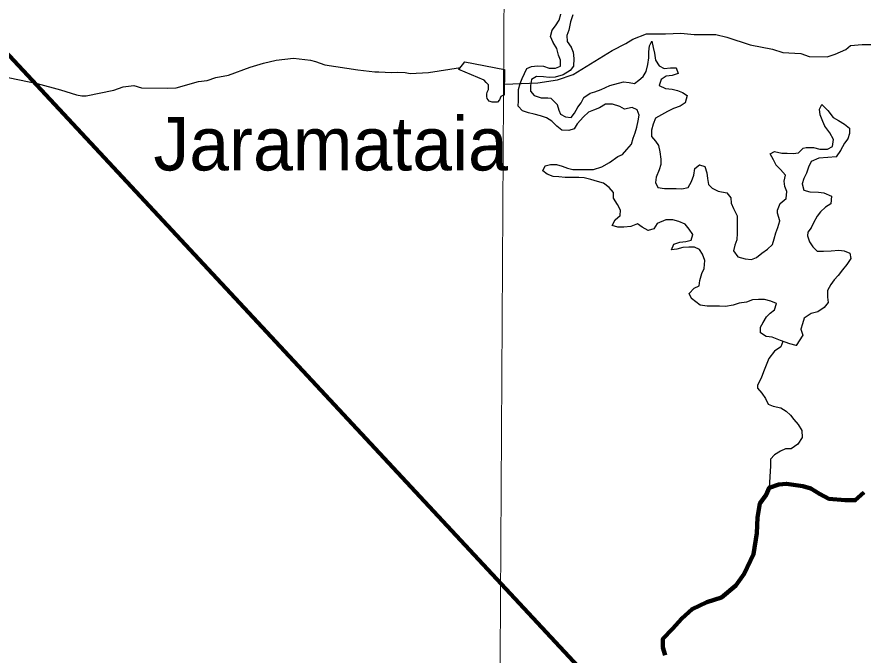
# Model space of a CAD drawing. Extents: x -1643653 to 4543381, y 1624270 to 13878484.
# Drawn here: x 714916 to 722813, y 8926255 to 8932209 of the extents above; entities that cross this region are included whole.
import ezdxf

# ---------------------------------------------------------------- set-up
doc = ezdxf.new("R2010")
doc.units = 0
doc.header["$LTSCALE"] = 200
for name, color, linetype, lineweight in [('1', 7, 'Continuous', 13), ('12', 7, 'Continuous', 25), ('21', 7, 'Continuous', 25), ('24', 7, 'Continuous', 25), ('53', 7, 'Continuous', 106), ('60', 7, 'Continuous', 13), ('9', 7, 'Continuous', 90)]:
    doc.layers.add(name, color=color, linetype=linetype, lineweight=lineweight)
doc.layers.add('41', color=7, linetype='Continuous')

msp = doc.modelspace()

# ---------------------------------------------------------------- linework, layer by layer
at = {"layer": '1'}
msp.add_lwpolyline([(719978.9, 9023574.5), (719561.6, 8949232.2), (719215.6, 8890710.6)], dxfattribs=at)
at = {"layer": '12'}
for points in [[(719465.7, 8931582), (719776.2, 8931594.6), (719960.1, 8931621.3), (720108, 8931671.9), (720470.6, 8931895.4), (720598.2, 8931961.4), (720664.5, 8932002), (720792.1, 8932052.7), (720970.4, 8932052.4), (721113, 8932057.2), (721235.3, 8932046.8), (721439, 8932046.4), (721540.8, 8932020.8), (721759.6, 8931949.1), (721968.3, 8931907.9), (722065, 8931877.2), (722233.1, 8931866.7), (722309.4, 8931841.1), (722477.5, 8931835.7), (722554, 8931861), (722651, 8931906.7), (722697, 8931942.3), (722804, 8931952.2), (722928.4, 8931953)], [(716324.2, 8931543.6), (716403.5, 8931548.6), (716611, 8931605.6), (716690.2, 8931616.7), (716773.7, 8931642.7), (716891.8, 8931664.4), (717093.4, 8931739.1), (717215.6, 8931777.9), (717335.2, 8931806.9), (717497.8, 8931823.2), (717656.3, 8931805.2), (717701.6, 8931794.1), (717788.3, 8931763.5), (718097.5, 8931715.5), (718256.9, 8931697.3), (718293.2, 8931696)], [(718293.2, 8931696), (718411.2, 8931691.7), (718463.6, 8931694.9), (718539.5, 8931689.8), (718584.8, 8931680.8), (718757, 8931689.8), (719057.1, 8931737.7)], [(714667.4, 8931678.5), (715103.5, 8931588.9), (715323.4, 8931530.2), (715472.8, 8931481.2), (715522.4, 8931471.9), (715561.6, 8931473.7), (715819.4, 8931527.1), (715907.5, 8931556.1), (716007, 8931568.4), (716078.4, 8931547.1), (716324.2, 8931543.6)]]:
    msp.add_lwpolyline(points, dxfattribs=at)
at = {"layer": '21'}
msp.add_lwpolyline([(719466.9, 8931717.9), (719464.5, 8931480.1), (719451.4, 8931477.4), (719431, 8931467.2), (719420.8, 8931436.5), (719400.5, 8931413.5), (719380.2, 8931413.5), (719352.2, 8931413.5), (719324.2, 8931423.7), (719306.3, 8931446.7), (719301.3, 8931467.1), (719301.2, 8931487.6), (719306.3, 8931508), (719316.5, 8931531.1), (719316.5, 8931554.1), (719316.5, 8931577.1), (719296.1, 8931597.5), (719278.3, 8931620.5), (719041.6, 8931717.6), (719097.6, 8931791.8)], close=True, dxfattribs=at)
at = {"layer": '24', "lineweight": 13}
for points in [[(720541.5, 8931374.6), (720475.5, 8931395.4), (720409.4, 8931395.9), (720353.4, 8931360.9), (720298.5, 8931340.7), (720249.5, 8931320.4), (720203.3, 8931277.1), (720145.5, 8931210.6), (720116.7, 8931164.4), (720066.9, 8931148.5), (720000.8, 8931154), (719955.3, 8931189.9), (719909.8, 8931236.1), (719859.2, 8931266.9), (719803.4, 8931287.7), (719742.5, 8931303.4), (719691.7, 8931313.9), (719635.9, 8931334.6), (719595.5, 8931375.6), (719595.8, 8931426.6), (719596.2, 8931482.6), (719596.6, 8931533.5), (719612.2, 8931589.4), (719632.8, 8931635.2), (719653.5, 8931680.9), (719674.2, 8931726.6), (719720.1, 8931746.7), (719776.1, 8931751.4), (719832, 8931751), (719882.7, 8931730.3), (719943.8, 8931729.9), (719989.7, 8931750), (719990.1, 8931806.1), (719970, 8931852), (719955.2, 8931913.3), (719920, 8931969.5), (719894.9, 8932025.7), (719910.6, 8932086.7), (719941.4, 8932127.3), (719977.3, 8932178), (719993, 8932233.9)], [(720104.8, 8932228.1), (720084.1, 8932162), (720068.3, 8932085.7), (720047.6, 8932034.9), (720052.3, 8931978.8), (720087.5, 8931927.7), (720107.6, 8931881.7), (720112.2, 8931820.6), (720111.7, 8931749.2), (720080.9, 8931708.7), (720014.5, 8931668.4), (719938.1, 8931648.5)], [(719938.1, 8931648.5), (719882.1, 8931643.8), (719831.3, 8931649.2), (719765.2, 8931654.7), (719719.2, 8931624.4), (719708.7, 8931568.5), (719708.3, 8931517.5), (719743.7, 8931476.5), (719809.6, 8931455.7), (719870.7, 8931455.3), (719899.8, 8931451.2), (719959.3, 8931391.6), (719974.2, 8931339.4), (719989.1, 8931302.2), (720037.3, 8931276), (720088.1, 8931270.6), (720118.9, 8931311.1), (720149.8, 8931367), (720180.6, 8931407.5), (720206.4, 8931458.3), (720267.7, 8931498.7), (720309.2, 8931510.9), (720368.7, 8931533.2), (720450.6, 8931570.5), (720578.7, 8931603.6), (720629.5, 8931598.2), (720680.3, 8931587.7), (720721.2, 8931618), (720762.1, 8931653.4), (720787.8, 8931699.1), (720803.6, 8931765.2), (720814.2, 8931826.2), (720814.5, 8931882.3), (720820, 8931938.3), (720840.7, 8931984), (720855.5, 8931922.8), (720865.3, 8931871.8), (720875.1, 8931805.5), (720910.3, 8931754.3), (720955.9, 8931728.6), (721017, 8931733.3), (721067.8, 8931732.9), (721087.8, 8931681.9), (721031.7, 8931661.8), (720975.8, 8931657.1), (720929.8, 8931626.8), (720909, 8931570.9), (720969.9, 8931540), (721030.9, 8931534.5), (721081.7, 8931524), (721127.3, 8931503.3), (721172.9, 8931477.6), (721152, 8931406.4), (721106.1, 8931376.1), (721044.9, 8931356.1), (720988.7, 8931325.9), (720932.6, 8931295.7), (720876.4, 8931265.5), (720855.7, 8931209.6), (720840.1, 8931153.7), (720839.6, 8931092.6), (720875, 8931051.6), (720905.2, 8931010.6), (720914.9, 8930949.5), (720924.7, 8930883.2), (720924.3, 8930832.2), (720908.7, 8930781.4), (720882.8, 8930715.3), (720877.4, 8930664.4), (720897.4, 8930618.5), (720958.4, 8930607.9), (721019.4, 8930607.5), (721070.3, 8930607.2), (721121.1, 8930606.8), (721182.2, 8930616.6), (721213.1, 8930672.5), (721233.9, 8930733.5), (721244.5, 8930794.5), (721285.4, 8930829.9), (721336.2, 8930814.3), (721356.1, 8930753.1), (721360.8, 8930702.1), (721370.6, 8930646), (721406, 8930610.1), (721461.7, 8930584.3), (721543, 8930568.5), (721578.3, 8930522.4), (721583, 8930471.4), (721603, 8930420.4), (721638.2, 8930353.9), (721637.8, 8930292.8), (721637.4, 8930241.9), (721637.1, 8930190.9), (721636.6, 8930129.8), (721615.9, 8930079), (721605.4, 8930028.1), (721645.7, 8929971.8), (721711.7, 8929951), (721772.7, 8929945.6), (721818.6, 8929965.6), (721869.7, 8930006.1)], [(722189.3, 8929143.2), (722128.4, 8929158.8), (722042.1, 8929189.9), (721966.1, 8929221), (721910.2, 8929226.4), (721854.5, 8929262.5), (721854.8, 8929313.4), (721880.6, 8929359.1), (721911.4, 8929409.8), (721947.3, 8929445.2), (721988.2, 8929475.5), (722003.8, 8929536.6), (721953.1, 8929557.3), (721892.2, 8929572.9), (721836.2, 8929573.3), (721780.3, 8929568.6), (721724.2, 8929548.6), (721658, 8929538.8), (721601.9, 8929518.8), (721530.6, 8929509), (721474.7, 8929509.4), (721418.7, 8929509.8), (721357.7, 8929510.2), (721291.7, 8929520.8), (721251.2, 8929551.6), (721210.7, 8929582.4), (721190.7, 8929628.4), (721236.8, 8929679), (721282.7, 8929699.1), (721288.2, 8929750), (721309, 8929816.1), (721329.6, 8929861.8), (721335.2, 8929938.2), (721315.3, 8929994.3), (721285.1, 8930040.4), (721239.4, 8930061), (721188.6, 8930061.4), (721132.6, 8930056.6), (721076.5, 8930041.7), (721025.6, 8930036.9), (721046.3, 8930087.8), (721102.4, 8930107.8), (721158.4, 8930112.5), (721209.4, 8930127.5), (721225, 8930178.3), (721189.7, 8930229.5), (721154.4, 8930275.5), (721093.6, 8930301.4), (721037.7, 8930317), (720971.6, 8930317.4), (720890, 8930282.3), (720859.1, 8930231.6), (720808.2, 8930216.6), (720752.4, 8930247.6), (720706.9, 8930278.4), (720645.7, 8930253.3), (720579.5, 8930248.7), (720523.6, 8930249), (720472.8, 8930264.6), (720498.6, 8930315.4), (720544.7, 8930355.8), (720550.1, 8930406.8), (720519.9, 8930457.9), (720484.7, 8930519.2), (720485.1, 8930570.2), (720444.7, 8930616.3), (720389.1, 8930657.4), (720333.2, 8930673), (720272.3, 8930693.8), (720211.4, 8930709.5), (720160.5, 8930709.8), (720094.4, 8930710.2), (720033.4, 8930710.6), (719972.4, 8930716.1), (719921.6, 8930721.5), (719865.8, 8930742.2), (719825.3, 8930773.1), (719845.9, 8930818.8), (719896.9, 8930833.7), (719952.8, 8930833.4), (720003.6, 8930817.8), (720054.3, 8930797.1), (720105.1, 8930786.6), (720166.2, 8930786.2), (720232.3, 8930785.7), (720298.4, 8930785.3), (720374.8, 8930810.3), (720446.3, 8930850.6), (720523, 8930906.1), (720568.9, 8930926.2), (720609.9, 8930971.8), (720651, 8931022.5), (720666.6, 8931078.4), (720687.3, 8931129.2), (720702.9, 8931180), (720713.5, 8931241.1), (720724, 8931292), (720704, 8931343), (720658.4, 8931363.7), (720587.1, 8931348.9), (720541.5, 8931374.6)], [(721869.7, 8930006.1), (721920.8, 8930041.4), (721966.9, 8930086.9), (721982.5, 8930137.8), (721998.2, 8930193.7), (722018.9, 8930244.5), (722035.3, 8930306.7), (722014.7, 8930377), (722015.4, 8930406.4), (722040.8, 8930468.5), (722095, 8930516.1), (722102.6, 8930580.2), (722082.5, 8930626.2), (722077.8, 8930677.1), (722088.4, 8930733.1), (722042.9, 8930784.3), (722002.5, 8930825.3), (721977.5, 8930876.4), (721947.3, 8930932.7), (721985.5, 8930954.9), (722054.2, 8930937.1), (722105, 8930936.7), (722161, 8930936.4), (722211.9, 8930941.1), (722254.4, 8930984.8), (722283.4, 8930991.6), (722349.5, 8930991.2), (722410.5, 8930975.5), (722481.7, 8930975.1), (722527.6, 8931000.2), (722538.2, 8931066.4), (722503.1, 8931127.7), (722457.7, 8931189.2), (722437.7, 8931235.1), (722412.7, 8931296.4), (722407.9, 8931347.4), (722428.6, 8931393.1), (722484.1, 8931336.7), (722534.6, 8931270.2), (722585.2, 8931244.4), (722640.9, 8931208.4), (722686.5, 8931172.4), (722686.1, 8931121.5), (722670.5, 8931070.6), (722639.7, 8931030.1), (722603.7, 8930964.1), (722562.5, 8930903.2), (722483.5, 8930896.6), (722400.2, 8930890.6), (722328.7, 8930860.8), (722304.9, 8930807.2), (722286.8, 8930752.2), (722261.1, 8930701.4), (722245.5, 8930650.6), (722260.3, 8930594.4), (722316.2, 8930578.8), (722397.5, 8930573.2), (722448.3, 8930567.8), (722519.3, 8930536.8), (722513.8, 8930465.5), (722462.7, 8930435.2), (722416.6, 8930389.7), (722385.8, 8930349.1), (722349.8, 8930288.2), (722329.1, 8930242.5), (722298.3, 8930202), (722294.2, 8930167.1), (722313, 8930110.2), (722343.2, 8930064.2), (722383.6, 8930023.1), (722444.6, 8930022.8), (722515.8, 8930027.4), (722587.1, 8930032), (722637.9, 8930026.6), (722688.6, 8930005.9), (722698.4, 8929954.9), (722662.5, 8929899.1), (722621.4, 8929848.4), (722580.4, 8929797.8), (722544.5, 8929757.2), (722513.7, 8929711.6), (722482.8, 8929655.8), (722482.3, 8929594.6), (722487.1, 8929543.7), (722451.2, 8929498), (722389.8, 8929457.7), (722328.7, 8929442.8), (722262.3, 8929397.4), (722246.7, 8929346.5), (722231.1, 8929295.7), (722251, 8929239.5), (722189.3, 8929143.2)]]:
    msp.add_lwpolyline(points, dxfattribs=at)
at = {"layer": '24'}
for points in [[(720541.5, 8931374.6), (720475.5, 8931395.4), (720409.4, 8931395.9), (720353.4, 8931360.9), (720298.5, 8931340.7), (720249.5, 8931320.4), (720203.3, 8931277.1), (720145.5, 8931210.6), (720116.7, 8931164.4), (720066.9, 8931148.5), (720000.8, 8931154), (719955.3, 8931189.9), (719909.8, 8931236.1), (719859.2, 8931266.9), (719803.4, 8931287.7), (719742.5, 8931303.4), (719691.7, 8931313.9), (719635.9, 8931334.6), (719595.5, 8931375.6), (719595.8, 8931426.6), (719596.2, 8931482.6), (719596.6, 8931533.5), (719612.2, 8931589.4), (719632.8, 8931635.2), (719653.5, 8931680.9), (719674.2, 8931726.6), (719720.1, 8931746.7), (719776.1, 8931751.4), (719832, 8931751), (719882.7, 8931730.3), (719943.8, 8931729.9), (719989.7, 8931750), (719990.1, 8931806.1), (719970, 8931852), (719955.2, 8931913.3), (719920, 8931969.5), (719894.9, 8932025.7), (719910.6, 8932086.7), (719941.4, 8932127.3), (719977.3, 8932178), (719993, 8932233.9)], [(720104.8, 8932228.1), (720084.1, 8932162), (720068.3, 8932085.7), (720047.6, 8932034.9), (720052.3, 8931978.8), (720087.5, 8931927.7), (720107.6, 8931881.7), (720112.2, 8931820.6), (720111.7, 8931749.2), (720080.9, 8931708.7), (720014.5, 8931668.4), (719938.1, 8931648.5)], [(719938.1, 8931648.5), (719882.1, 8931643.8), (719831.3, 8931649.2), (719765.2, 8931654.7), (719719.2, 8931624.4), (719708.7, 8931568.5), (719708.3, 8931517.5), (719743.7, 8931476.5), (719809.6, 8931455.7), (719870.7, 8931455.3), (719899.8, 8931451.2), (719959.3, 8931391.6), (719974.2, 8931339.4), (719989.1, 8931302.2), (720037.3, 8931276), (720088.1, 8931270.6), (720118.9, 8931311.1), (720149.8, 8931367), (720180.6, 8931407.5), (720206.4, 8931458.3), (720267.7, 8931498.7), (720309.2, 8931510.9), (720368.7, 8931533.2), (720450.6, 8931570.5), (720578.7, 8931603.6), (720629.5, 8931598.2), (720680.3, 8931587.7), (720721.2, 8931618), (720762.1, 8931653.4), (720787.8, 8931699.1), (720803.6, 8931765.2), (720814.2, 8931826.2), (720814.5, 8931882.3), (720820, 8931938.3), (720840.7, 8931984), (720855.5, 8931922.8), (720865.3, 8931871.8), (720875.1, 8931805.5), (720910.3, 8931754.3), (720955.9, 8931728.6), (721017, 8931733.3), (721067.8, 8931732.9), (721087.8, 8931681.9), (721031.7, 8931661.8), (720975.8, 8931657.1), (720929.8, 8931626.8), (720909, 8931570.9), (720969.9, 8931540), (721030.9, 8931534.5), (721081.7, 8931524), (721127.3, 8931503.3), (721172.9, 8931477.6), (721152, 8931406.4), (721106.1, 8931376.1), (721044.9, 8931356.1), (720988.7, 8931325.9), (720932.6, 8931295.7), (720876.4, 8931265.5), (720855.7, 8931209.6), (720840.1, 8931153.7), (720839.6, 8931092.6), (720875, 8931051.6), (720905.2, 8931010.6), (720914.9, 8930949.5), (720924.7, 8930883.2), (720924.3, 8930832.2), (720908.7, 8930781.4), (720882.8, 8930715.3), (720877.4, 8930664.4), (720897.4, 8930618.5), (720958.4, 8930607.9), (721019.4, 8930607.5), (721070.3, 8930607.2), (721121.1, 8930606.8), (721182.2, 8930616.6), (721213.1, 8930672.5), (721233.9, 8930733.5), (721244.5, 8930794.5), (721285.4, 8930829.9), (721336.2, 8930814.3), (721356.1, 8930753.1), (721360.8, 8930702.1), (721370.6, 8930646), (721406, 8930610.1), (721461.7, 8930584.3), (721543, 8930568.5), (721578.3, 8930522.4), (721583, 8930471.4), (721603, 8930420.4), (721638.2, 8930353.9), (721637.8, 8930292.8), (721637.4, 8930241.9), (721637.1, 8930190.9), (721636.6, 8930129.8), (721615.9, 8930079), (721605.4, 8930028.1), (721645.7, 8929971.8), (721711.7, 8929951), (721772.7, 8929945.6), (721818.6, 8929965.6), (721869.7, 8930006.1)], [(722189.3, 8929143.2), (722128.4, 8929158.8), (722042.1, 8929189.9), (721966.1, 8929221), (721910.2, 8929226.4), (721854.5, 8929262.5), (721854.8, 8929313.4), (721880.6, 8929359.1), (721911.4, 8929409.8), (721947.3, 8929445.2), (721988.2, 8929475.5), (722003.8, 8929536.6), (721953.1, 8929557.3), (721892.2, 8929572.9), (721836.2, 8929573.3), (721780.3, 8929568.6), (721724.2, 8929548.6), (721658, 8929538.8), (721601.9, 8929518.8), (721530.6, 8929509), (721474.7, 8929509.4), (721418.7, 8929509.8), (721357.7, 8929510.2), (721291.7, 8929520.8), (721251.2, 8929551.6), (721210.7, 8929582.4), (721190.7, 8929628.4), (721236.8, 8929679), (721282.7, 8929699.1), (721288.2, 8929750), (721309, 8929816.1), (721329.6, 8929861.8), (721335.2, 8929938.2), (721315.3, 8929994.3), (721285.1, 8930040.4), (721239.4, 8930061), (721188.6, 8930061.4), (721132.6, 8930056.6), (721076.5, 8930041.7), (721025.6, 8930036.9), (721046.3, 8930087.8), (721102.4, 8930107.8), (721158.4, 8930112.5), (721209.4, 8930127.5), (721225, 8930178.3), (721189.7, 8930229.5), (721154.4, 8930275.5), (721093.6, 8930301.4), (721037.7, 8930317), (720971.6, 8930317.4), (720890, 8930282.3), (720859.1, 8930231.6), (720808.2, 8930216.6), (720752.4, 8930247.6), (720706.9, 8930278.4), (720645.7, 8930253.3), (720579.5, 8930248.7), (720523.6, 8930249), (720472.8, 8930264.6), (720498.6, 8930315.4), (720544.7, 8930355.8), (720550.1, 8930406.8), (720519.9, 8930457.9), (720484.7, 8930519.2), (720485.1, 8930570.2), (720444.7, 8930616.3), (720389.1, 8930657.4), (720333.2, 8930673), (720272.3, 8930693.8), (720211.4, 8930709.5), (720160.5, 8930709.8), (720094.4, 8930710.2), (720033.4, 8930710.6), (719972.4, 8930716.1), (719921.6, 8930721.5), (719865.8, 8930742.2), (719825.3, 8930773.1), (719845.9, 8930818.8), (719896.9, 8930833.7), (719952.8, 8930833.4), (720003.6, 8930817.8), (720054.3, 8930797.1), (720105.1, 8930786.6), (720166.2, 8930786.2), (720232.3, 8930785.7), (720298.4, 8930785.3), (720374.8, 8930810.3), (720446.3, 8930850.6), (720523, 8930906.1), (720568.9, 8930926.2), (720609.9, 8930971.8), (720651, 8931022.5), (720666.6, 8931078.4), (720687.3, 8931129.2), (720702.9, 8931180), (720713.5, 8931241.1), (720724, 8931292), (720704, 8931343), (720658.4, 8931363.7), (720587.1, 8931348.9), (720541.5, 8931374.6)], [(721869.7, 8930006.1), (721920.8, 8930041.4), (721966.9, 8930086.9), (721982.5, 8930137.8), (721998.2, 8930193.7), (722018.9, 8930244.5), (722035.3, 8930306.7), (722014.7, 8930377), (722015.4, 8930406.4), (722040.8, 8930468.5), (722095, 8930516.1), (722102.6, 8930580.2), (722082.5, 8930626.2), (722077.8, 8930677.1), (722088.4, 8930733.1), (722042.9, 8930784.3), (722002.5, 8930825.3), (721977.5, 8930876.4), (721947.3, 8930932.7), (721985.5, 8930954.9), (722054.2, 8930937.1), (722105, 8930936.7), (722161, 8930936.4), (722211.9, 8930941.1), (722254.4, 8930984.8), (722283.4, 8930991.6), (722349.5, 8930991.2), (722410.5, 8930975.5), (722481.7, 8930975.1), (722527.6, 8931000.2), (722538.2, 8931066.4), (722503.1, 8931127.7), (722457.7, 8931189.2), (722437.7, 8931235.1), (722412.7, 8931296.4), (722407.9, 8931347.4), (722428.6, 8931393.1), (722484.1, 8931336.7), (722534.6, 8931270.2), (722585.2, 8931244.4), (722640.9, 8931208.4), (722686.5, 8931172.4), (722686.1, 8931121.5), (722670.5, 8931070.6), (722639.7, 8931030.1), (722603.7, 8930964.1), (722562.5, 8930903.2), (722483.5, 8930896.6), (722400.2, 8930890.6), (722328.7, 8930860.8), (722304.9, 8930807.2), (722286.8, 8930752.2), (722261.1, 8930701.4), (722245.5, 8930650.6), (722260.3, 8930594.4), (722316.2, 8930578.8), (722397.5, 8930573.2), (722448.3, 8930567.8), (722519.3, 8930536.8), (722513.8, 8930465.5), (722462.7, 8930435.2), (722416.6, 8930389.7), (722385.8, 8930349.1), (722349.8, 8930288.2), (722329.1, 8930242.5), (722298.3, 8930202), (722294.2, 8930167.1), (722313, 8930110.2), (722343.2, 8930064.2), (722383.6, 8930023.1), (722444.6, 8930022.8), (722515.8, 8930027.4), (722587.1, 8930032), (722637.9, 8930026.6), (722688.6, 8930005.9), (722698.4, 8929954.9), (722662.5, 8929899.1), (722621.4, 8929848.4), (722580.4, 8929797.8), (722544.5, 8929757.2), (722513.7, 8929711.6), (722482.8, 8929655.8), (722482.3, 8929594.6), (722487.1, 8929543.7), (722451.2, 8929498), (722389.8, 8929457.7), (722328.7, 8929442.8), (722262.3, 8929397.4), (722246.7, 8929346.5), (722231.1, 8929295.7), (722251, 8929239.5), (722189.3, 8929143.2)], [(722065, 8929181.7), (722047.1, 8929132.1), (721985.8, 8929091.8), (721934.5, 8929020.8), (721908.6, 8928959.8), (721882.8, 8928898.9), (721862, 8928837.9), (721836.2, 8928792.2), (721826.6, 8928771.5)], [(721826.6, 8928771.5), (721827.2, 8928745.6), (721867.6, 8928699.5), (721902.9, 8928648.4), (721927.9, 8928597.3), (721973.6, 8928576.7), (722044.7, 8928561), (722095.3, 8928530.1), (722135.8, 8928494.2), (722166, 8928453.3), (722206.3, 8928407.2), (722241.6, 8928351), (722246.2, 8928284.7), (722205.1, 8928223.9), (722143.7, 8928178.4), (722087.8, 8928178.8), (722041.9, 8928158.7), (721985.7, 8928123.4), (721949.8, 8928082.9), (721949.4, 8928021.8), (721938.1, 8927816.7)]]:
    msp.add_lwpolyline(points, dxfattribs=at)
at = {"layer": '24', "lineweight": 53}
msp.add_lwpolyline([(722821.3, 8927772.9), (722741, 8927699.8), (722646.1, 8927699.8), (722492.8, 8927714.4), (722405.2, 8927758.2), (722325, 8927809.4), (722252, 8927831.3), (722098.7, 8927853.2), (722025.7, 8927845.9), (721938.1, 8927816.7), (721908.9, 8927750.9), (721850.6, 8927670.6), (721828.7, 8927539.1), (721821.3, 8927392.9), (721792.2, 8927195.7), (721704.6, 8927013), (721624.3, 8926903.4), (721492.9, 8926793.8), (721354.2, 8926750), (721217.7, 8926684.8), (721120.7, 8926596.5), (721033.1, 8926501.5), (720945.5, 8926406.6), (720945.5, 8926326.2), (720967.4, 8926253.1)], dxfattribs=at)
at = {"layer": '53'}
msp.add_lwpolyline([(722821.3, 8927772.9), (722741, 8927699.8), (722646.1, 8927699.8), (722492.8, 8927714.4), (722405.2, 8927758.2), (722325, 8927809.4), (722252, 8927831.3), (722098.7, 8927853.2), (722025.7, 8927845.9), (721938.1, 8927816.7), (721908.9, 8927750.9), (721850.6, 8927670.6), (721828.7, 8927539.1), (721821.3, 8927392.9), (721792.2, 8927195.7), (721704.6, 8927013), (721624.3, 8926903.4), (721492.9, 8926793.8), (721354.2, 8926750), (721217.7, 8926684.8), (721120.7, 8926596.5), (721033.1, 8926501.5), (720945.5, 8926406.6), (720945.5, 8926326.2), (720967.4, 8926253.1)], dxfattribs=at)
msp.add_lwpolyline([(722821.3, 8927772.9), (722741, 8927699.8), (722646.1, 8927699.8), (722492.8, 8927714.4), (722405.2, 8927758.2), (722325, 8927809.4), (722252, 8927831.3), (722098.7, 8927853.2), (722025.7, 8927845.9), (721938.1, 8927816.7), (721908.9, 8927750.9), (721850.6, 8927670.6), (721828.7, 8927539.1), (721821.3, 8927392.9), (721792.2, 8927195.7), (721704.6, 8927013), (721624.3, 8926903.4), (721492.9, 8926793.8), (721354.2, 8926750), (721217.7, 8926684.8), (721120.7, 8926596.5), (721033.1, 8926501.5), (720945.5, 8926406.6), (720945.5, 8926326.2), (720967.4, 8926253.1)], dxfattribs=at)
msp.add_lwpolyline([(722821.3, 8927772.9), (722741, 8927699.8), (722646.1, 8927699.8), (722492.8, 8927714.4), (722405.2, 8927758.2), (722325, 8927809.4), (722252, 8927831.3), (722098.7, 8927853.2), (722025.7, 8927845.9), (721938.1, 8927816.7), (721908.9, 8927750.9), (721850.6, 8927670.6), (721828.7, 8927539.1), (721821.3, 8927392.9), (721792.2, 8927195.7), (721704.6, 8927013), (721624.3, 8926903.4), (721492.9, 8926793.8), (721354.2, 8926750), (721217.7, 8926684.8), (721120.7, 8926596.5), (721033.1, 8926501.5), (720945.5, 8926406.6), (720945.5, 8926326.2), (720967.4, 8926253.1)], dxfattribs=at)
at = {"layer": '60', "lineweight": 25}
msp.add_spline([(814781, 9009175.5), (814787.2, 9009173.4), (814796.9, 9009173.4), (814799.4, 9009172.4), (814805.1, 9009174.5), (814805.6, 9009176.5), (814811.7, 9009179.5), (814811.7, 9009179.5), (814801.5, 9009181), (814790.7, 9009181.5), (814784.1, 9009183.1), (814777.4, 9009185.1), (814778.4, 9009175.5)], degree=3, dxfattribs=at)
at = {"layer": '9'}
msp.add_line((710319.1, 8936704.6), (720989.4, 8925252.2), dxfattribs=at)
msp.add_lwpolyline([(722821.3, 8927772.9), (722741, 8927699.8), (722646.1, 8927699.8), (722492.8, 8927714.4), (722405.2, 8927758.2), (722325, 8927809.4), (722252, 8927831.3), (722098.7, 8927853.2), (722025.7, 8927845.9), (721938.1, 8927816.7), (721908.9, 8927750.9), (721850.6, 8927670.6), (721828.7, 8927539.1), (721821.3, 8927392.9), (721792.2, 8927195.7), (721704.6, 8927013), (721624.3, 8926903.4), (721492.9, 8926793.8), (721354.2, 8926750), (721217.7, 8926684.8), (721120.7, 8926596.5), (721033.1, 8926501.5), (720945.5, 8926406.6), (720945.5, 8926326.2), (720967.4, 8926253.1)], dxfattribs=at)

# ---------------------------------------------------------------- texts
at = {"layer": '41'}
msp.add_text('Jaramataia', height=500, dxfattribs=at).set_placement((716190.3, 8930776.7))

doc.saveas('drawing.dxf')
